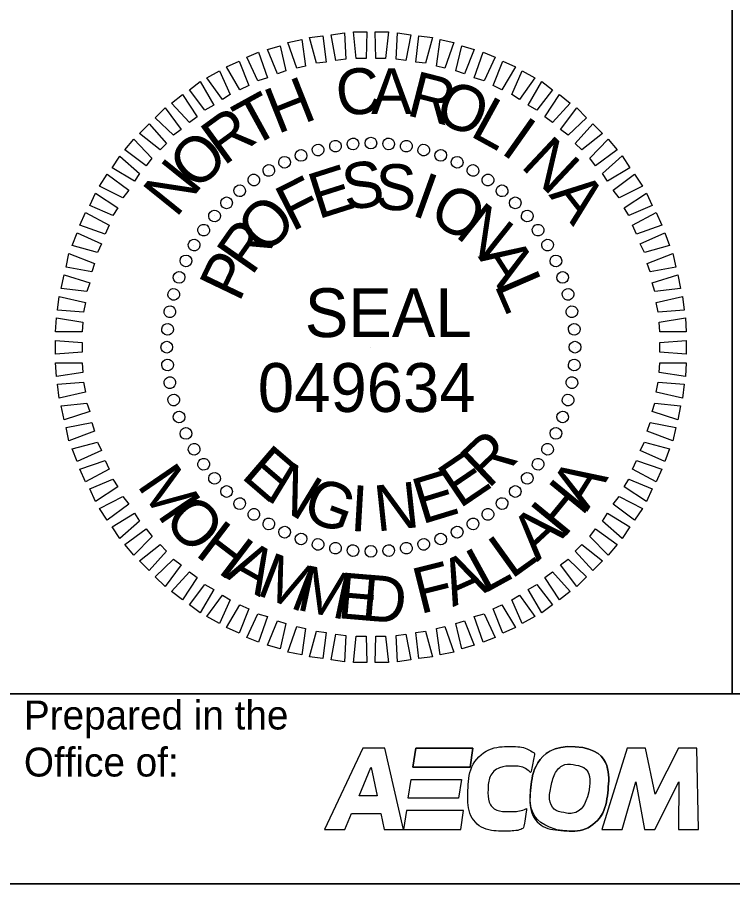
# Model space of a CAD drawing. Extents: x 2113763 to 2114783, y 714280 to 714940.
# Drawn here: x 2114643.5 to 2114702.8, y 714819.5 to 714891.4 of the extents above; entities that cross this region are included whole.
import ezdxf

# ---------------------------------------------------------------- set-up
doc = ezdxf.new("R2010")
doc.units = 0
for name, color, linetype in [('Default', 7, 'Continuous'), ('Prop DSN Text', 7, 'Continuous'), ('Sheet Block Title CELL', 7, 'Continuous'), ('Sheet Border Standard 30in CELL', 7, 'Continuous'), ('Sheet Professional Seal CELL', 7, 'Continuous'), ('Sheet Sticker Exception Certification CELL', 7, 'Continuous')]:
    doc.layers.add(name, color=color, linetype=linetype)

# ---------------------------------------------------------------- blocks, each defined once
blk = doc.blocks.new('block 3')
at = {"layer": 'Default'}
blk.add_open_spline([(0.12275, 0.09393), (0.12554, 0.09373), (0.12726, 0.09146), (0.12695, 0.08843), (0.12663, 0.08531), (0.12411, 0.08298), (0.12127, 0.08318), (0.11848, 0.08338), (0.11676, 0.08565), (0.11707, 0.08868), (0.11739, 0.0918), (0.11991, 0.09413), (0.12275, 0.09393)], degree=3, dxfattribs=at)
blk = doc.blocks.new('block 2')
at = {"layer": 'Default'}
for p, q in [((0.10234, 0.09375), (0.10197, 0.09133)), ((0.10966, 0.09375), (0.10234, 0.09375)), ((0.10929, 0.09133), (0.10966, 0.09375)), ((0.10197, 0.09133), (0.10929, 0.09133)), ((0.10137, 0.08733), (0.10174, 0.08975)), ((0.10174, 0.08975), (0.10818, 0.08975)), ((0.10818, 0.08975), (0.10782, 0.08733)), ((0.10782, 0.08733), (0.10137, 0.08733)), ((0.10114, 0.08576), (0.10078, 0.08333)), ((0.10846, 0.08576), (0.10114, 0.08576)), ((0.1081, 0.08333), (0.10846, 0.08576)), ((0.10078, 0.08333), (0.1081, 0.08333))]:
    blk.add_line(p, q, dxfattribs=at)
for points in [[(0.10929, 0.09133), (0.10197, 0.09133), (0.10234, 0.09375), (0.10966, 0.09375), (0.10929, 0.09133)], [(0.10782, 0.08733), (0.10137, 0.08733), (0.10174, 0.08975), (0.10818, 0.08975), (0.10782, 0.08733)], [(0.10846, 0.08576), (0.10114, 0.08576), (0.10078, 0.08333), (0.1081, 0.08333), (0.10846, 0.08576)]]:
    blk.add_lwpolyline(points, dxfattribs=at)
blk = doc.blocks.new('POINT_DISPLAY')
at = {"layer": 'Default'}
blk.add_line((0, 0), (0, 0), dxfattribs=at)

msp = doc.modelspace()

# ---------------------------------------------------------------- linework, layer by layer
at = {"layer": 'Prop DSN Text'}
for p, q in [((2114672.112, 714830.749), (2114668.936, 714823.999)), ((2114673.94, 714830.749), (2114672.112, 714830.749)), ((2114675.5, 714823.999), (2114673.94, 714830.749)), ((2114694.058, 714830.75), (2114691.961, 714823.999)), ((2114695.578, 714830.75), (2114694.058, 714830.75)), ((2114696.365, 714826.942), (2114695.578, 714830.75)), ((2114698.313, 714830.75), (2114696.365, 714826.942)), ((2114699.835, 714830.75), (2114698.313, 714830.75)), ((2114699.959, 714823.999), (2114699.835, 714830.75)), ((2114671.807, 714826.802), (2114672.787, 714829.143)), ((2114672.787, 714829.143), (2114672.802, 714829.143)), ((2114672.802, 714829.143), (2114673.299, 714826.802)), ((2114693.638, 714823.999), (2114694.78, 714827.951)), ((2114694.78, 714827.951), (2114695.497, 714823.999)), ((2114696.352, 714823.999), (2114698.33, 714827.949)), ((2114698.33, 714827.949), (2114698.307, 714823.999)), ((2114673.299, 714826.802), (2114671.807, 714826.802)), ((2114670.634, 714823.999), (2114671.185, 714825.314)), ((2114671.185, 714825.314), (2114673.615, 714825.314)), ((2114673.615, 714825.314), (2114673.894, 714823.999)), ((2114668.936, 714823.999), (2114670.634, 714823.999)), ((2114673.894, 714823.999), (2114675.5, 714823.999)), ((2114691.961, 714823.999), (2114693.638, 714823.999)), ((2114695.497, 714823.999), (2114696.352, 714823.999)), ((2114698.307, 714823.999), (2114699.959, 714823.999))]:
    msp.add_line(p, q, dxfattribs=at)
for points in [[(2114673.894, 714823.999), (2114675.5, 714823.999), (2114673.94, 714830.749), (2114672.112, 714830.749), (2114668.936, 714823.999), (2114670.634, 714823.999), (2114671.185, 714825.314), (2114673.615, 714825.314), (2114673.894, 714823.999)], [(2114699.959, 714823.999), (2114699.835, 714830.75), (2114698.313, 714830.75), (2114696.365, 714826.942), (2114695.578, 714830.75), (2114694.058, 714830.75), (2114691.961, 714823.999), (2114693.638, 714823.999), (2114694.78, 714827.951), (2114695.497, 714823.999), (2114696.352, 714823.999), (2114698.33, 714827.949), (2114698.307, 714823.999), (2114699.959, 714823.999)]]:
    msp.add_lwpolyline(points, dxfattribs=at)
for points in [[(2114685.708, 714825.73), (2114685.255, 714825.521), (2114684.579, 714825.487), (2114684.248, 714825.487), (2114683.18, 714825.487), (2114682.473, 714826.215), (2114682.509, 714827.298), (2114682.547, 714828.442), (2114683.411, 714829.262), (2114684.585, 714829.262), (2114685.14, 714829.262), (2114685.629, 714829.078), (2114686.067, 714828.708), (2114686.067, 714828.708), (2114686.392, 714830.324), (2114686.392, 714830.324), (2114685.721, 714830.719), (2114685.159, 714830.881), (2114684.456, 714830.881), (2114682.513, 714830.881), (2114680.909, 714829.262), (2114680.841, 714827.227), (2114680.776, 714825.254), (2114682.058, 714823.867), (2114683.964, 714823.867), (2114684.295, 714823.867), (2114685.011, 714823.902), (2114685.463, 714824.11), (2114685.463, 714824.11), (2114685.708, 714825.73), (2114685.708, 714825.73)], [(2114685.708, 714825.73), (2114685.255, 714825.521), (2114684.579, 714825.487), (2114684.248, 714825.487), (2114683.18, 714825.487), (2114682.473, 714826.215), (2114682.509, 714827.298), (2114682.547, 714828.442), (2114683.411, 714829.262), (2114684.585, 714829.262), (2114685.14, 714829.262), (2114685.629, 714829.078), (2114686.067, 714828.708), (2114686.067, 714828.708), (2114686.392, 714830.324), (2114686.392, 714830.324), (2114685.721, 714830.719), (2114685.159, 714830.881), (2114684.456, 714830.881), (2114682.513, 714830.881), (2114680.909, 714829.262), (2114680.841, 714827.227), (2114680.776, 714825.254), (2114682.058, 714823.867), (2114683.964, 714823.867), (2114684.295, 714823.867), (2114685.011, 714823.902), (2114685.463, 714824.11), (2114685.463, 714824.11), (2114685.708, 714825.73), (2114685.708, 714825.73)], [(2114688.077, 714824.028), (2114686.692, 714824.442), (2114685.884, 714825.769), (2114686.058, 714827.464), (2114686.266, 714829.489), (2114687.9, 714830.996), (2114689.742, 714830.865)], [(2114689.742, 714830.865), (2114691.548, 714830.736), (2114692.664, 714829.267), (2114692.463, 714827.302), (2114692.255, 714825.278), (2114690.621, 714823.771), (2114688.778, 714823.902), (2114688.531, 714823.92), (2114688.297, 714823.962), (2114688.077, 714824.028)], [(2114690.857, 714827.138), (2114691.102, 714828.279), (2114690.677, 714829.168), (2114689.815, 714829.344), (2114688.867, 714829.539), (2114688.005, 714828.813), (2114687.745, 714827.607), (2114687.499, 714826.465), (2114687.924, 714825.577), (2114688.786, 714825.4), (2114689.735, 714825.206), (2114690.597, 714825.932), (2114690.857, 714827.138)], [(2114690.857, 714827.138), (2114691.102, 714828.279), (2114690.677, 714829.168), (2114689.815, 714829.344), (2114688.867, 714829.539), (2114688.005, 714828.813), (2114687.745, 714827.607), (2114687.499, 714826.465), (2114687.924, 714825.577), (2114688.786, 714825.4), (2114689.735, 714825.206), (2114690.597, 714825.932), (2114690.857, 714827.138)]]:
    msp.add_open_spline(points, degree=3, dxfattribs=at)
at = {"layer": 'Sheet Block Title CELL'}
msp.add_lwpolyline([(2114642.734, 714835.256), (2114762.735, 714835.256), (2114762.735, 714819.507), (2114642.734, 714819.507)], close=True, dxfattribs=at)
at = {"layer": 'Sheet Border Standard 30in CELL'}
for points in [[(2114642.734, 714902.756), (2114702.764, 714902.756), (2114702.764, 714835.256), (2114642.734, 714835.256)], [(2114702.764, 714902.756), (2114762.765, 714902.756), (2114762.765, 714835.256), (2114702.764, 714835.256)]]:
    msp.add_lwpolyline(points, close=True, dxfattribs=at)
at = {"layer": 'Sheet Professional Seal CELL'}
for points in [[(2114668.27, 714887.567), (2114667.696, 714889.694), (2114668.811, 714889.829), (2114669.081, 714887.668)], [(2114669.89, 714887.804), (2114669.486, 714889.931), (2114670.6, 714890.099), (2114670.701, 714887.905)], [(2114671.578, 714887.973), (2114671.343, 714890.167), (2114672.456, 714890.167), (2114672.389, 714887.973)], [(2114673.199, 714887.973), (2114673.132, 714890.167), (2114674.245, 714890.167), (2114674.009, 714887.973)], [(2114674.887, 714887.905), (2114674.988, 714890.099), (2114676.102, 714889.931), (2114675.697, 714887.804)], [(2114676.507, 714887.669), (2114676.777, 714889.83), (2114677.891, 714889.694), (2114677.317, 714887.568)], [(2114665.03, 714886.689), (2114664.219, 714888.714), (2114665.267, 714889.019), (2114665.738, 714886.926)], [(2114666.65, 714887.162), (2114665.907, 714889.289), (2114667.055, 714889.525), (2114667.358, 714887.331)], [(2114678.228, 714887.331), (2114678.533, 714889.525), (2114679.679, 714889.289), (2114678.938, 714887.162)], [(2114679.848, 714886.926), (2114680.321, 714889.019), (2114681.367, 714888.715), (2114680.558, 714886.689)], [(2114663.41, 714886.116), (2114662.498, 714888.074), (2114663.477, 714888.479), (2114664.219, 714886.352)], [(2114681.367, 714886.352), (2114682.11, 714888.479), (2114683.09, 714888.074), (2114682.178, 714886.116)], [(2114661.924, 714885.373), (2114660.81, 714887.263), (2114661.857, 714887.736), (2114662.667, 714885.711)], [(2114682.921, 714885.711), (2114683.73, 714887.736), (2114684.778, 714887.263), (2114683.664, 714885.373)], [(2114660.473, 714884.563), (2114659.191, 714886.351), (2114660.236, 714886.926), (2114661.114, 714884.968)], [(2114684.473, 714884.968), (2114685.352, 714886.926), (2114686.398, 714886.352), (2114685.115, 714884.563)], [(2114659.022, 714883.685), (2114657.738, 714885.373), (2114658.616, 714886.048), (2114659.763, 714884.091)], [(2114685.824, 714884.091), (2114686.972, 714886.049), (2114687.849, 714885.374), (2114686.566, 714883.686)], [(2114657.738, 714882.638), (2114656.253, 714884.26), (2114657.165, 714884.968), (2114658.38, 714883.111)], [(2114687.208, 714883.111), (2114688.423, 714884.968), (2114689.335, 714884.26), (2114687.849, 714882.638)], [(2114656.422, 714881.592), (2114654.903, 714883.043), (2114655.712, 714883.854), (2114657.063, 714882.065)], [(2114688.524, 714882.066), (2114689.874, 714883.854), (2114690.685, 714883.044), (2114689.166, 714881.593)], [(2114655.309, 714880.378), (2114653.586, 714881.728), (2114654.397, 714882.537), (2114655.848, 714880.917)], [(2114689.74, 714880.917), (2114691.191, 714882.537), (2114692.001, 714881.728), (2114690.28, 714880.378)], [(2114654.16, 714879.06), (2114652.371, 714880.378), (2114653.114, 714881.255), (2114654.633, 714879.702)], [(2114690.955, 714879.703), (2114692.474, 714881.255), (2114693.217, 714880.378), (2114691.428, 714879.061)], [(2114653.181, 714877.778), (2114651.324, 714878.892), (2114651.966, 714879.871), (2114653.586, 714878.419)], [(2114692.001, 714878.419), (2114693.622, 714879.872), (2114694.263, 714878.892), (2114692.406, 714877.778)], [(2114652.203, 714876.393), (2114650.278, 714877.373), (2114650.92, 714878.352), (2114652.709, 714877.035)], [(2114692.879, 714877.036), (2114694.668, 714878.352), (2114695.31, 714877.373), (2114693.386, 714876.394)], [(2114651.392, 714874.942), (2114649.468, 714875.753), (2114649.941, 714876.799), (2114651.797, 714875.584)], [(2114693.791, 714875.584), (2114695.648, 714876.799), (2114696.119, 714875.753), (2114694.195, 714874.942)], [(2114650.751, 714873.39), (2114648.658, 714874.132), (2114649.13, 714875.179), (2114651.089, 714874.133)], [(2114694.499, 714874.133), (2114696.457, 714875.179), (2114696.93, 714874.133), (2114694.837, 714873.39)], [(2114650.109, 714871.871), (2114648.016, 714872.445), (2114648.422, 714873.491), (2114650.447, 714872.579)], [(2114695.141, 714872.579), (2114697.167, 714873.491), (2114697.571, 714872.445), (2114695.479, 714871.871)], [(2114649.636, 714870.251), (2114647.51, 714870.655), (2114647.746, 714871.77), (2114649.873, 714870.959)], [(2114695.714, 714870.959), (2114697.842, 714871.77), (2114698.077, 714870.655), (2114695.95, 714870.251)], [(2114649.232, 714868.629), (2114647.105, 714868.866), (2114647.341, 714870.014), (2114649.468, 714869.339)], [(2114696.119, 714869.339), (2114698.246, 714870.014), (2114698.482, 714868.866), (2114696.356, 714868.629)], [(2114648.961, 714866.908), (2114646.802, 714867.077), (2114646.936, 714868.225), (2114649.13, 714867.719)], [(2114696.457, 714867.719), (2114698.651, 714868.225), (2114698.787, 714867.077), (2114696.626, 714866.909)], [(2114648.827, 714865.288), (2114646.633, 714865.288), (2114646.701, 714866.435), (2114648.895, 714866.098)], [(2114696.694, 714866.098), (2114698.888, 714866.435), (2114698.955, 714865.288), (2114696.761, 714865.288)], [(2114648.827, 714863.6), (2114646.633, 714863.432), (2114646.633, 714864.578), (2114648.827, 714864.41)], [(2114696.761, 714864.41), (2114698.955, 714864.579), (2114698.956, 714863.432), (2114696.761, 714863.601)], [(2114648.895, 714861.913), (2114646.701, 714861.575), (2114646.633, 714862.722), (2114648.827, 714862.722)], [(2114696.761, 714862.722), (2114698.955, 714862.722), (2114698.888, 714861.575), (2114696.694, 714861.913)], [(2114649.13, 714860.292), (2114646.936, 714859.786), (2114646.802, 714860.933), (2114648.961, 714861.102)], [(2114696.626, 714861.102), (2114698.787, 714860.934), (2114698.651, 714859.786), (2114696.457, 714860.293)], [(2114649.468, 714858.671), (2114647.341, 714857.996), (2114647.105, 714859.144), (2114649.232, 714859.381)], [(2114696.356, 714859.381), (2114698.483, 714859.145), (2114698.246, 714857.996), (2114696.12, 714858.672)], [(2114649.873, 714857.051), (2114647.747, 714856.242), (2114647.51, 714857.355), (2114649.637, 714857.761)], [(2114695.951, 714857.761), (2114698.077, 714857.356), (2114697.842, 714856.242), (2114695.714, 714857.051)], [(2114650.447, 714855.431), (2114648.422, 714854.519), (2114648.016, 714855.566), (2114650.11, 714856.139)], [(2114695.479, 714856.14), (2114697.571, 714855.567), (2114697.167, 714854.52), (2114695.141, 714855.431)], [(2114651.089, 714853.879), (2114649.13, 714852.831), (2114648.658, 714853.879), (2114650.752, 714854.62)], [(2114694.837, 714854.62), (2114696.93, 714853.879), (2114696.457, 714852.832), (2114694.499, 714853.879)], [(2114651.798, 714852.426), (2114649.941, 714851.211), (2114649.468, 714852.257), (2114651.392, 714853.068)], [(2114694.195, 714853.068), (2114696.119, 714852.258), (2114695.648, 714851.212), (2114693.791, 714852.426)], [(2114652.709, 714850.975), (2114650.92, 714849.659), (2114650.279, 714850.637), (2114652.203, 714851.617)], [(2114693.386, 714851.617), (2114695.31, 714850.638), (2114694.668, 714849.659), (2114692.88, 714850.975)], [(2114653.586, 714849.591), (2114651.966, 714848.14), (2114651.325, 714849.118), (2114653.181, 714850.232)], [(2114692.406, 714850.232), (2114694.263, 714849.119), (2114693.622, 714848.14), (2114692.001, 714849.592)], [(2114654.634, 714848.309), (2114653.115, 714846.755), (2114652.372, 714847.634), (2114654.161, 714848.949)], [(2114691.428, 714848.95), (2114693.217, 714847.634), (2114692.474, 714846.756), (2114690.955, 714848.309)], [(2114655.848, 714847.093), (2114654.397, 714845.473), (2114653.587, 714846.283), (2114655.309, 714847.634)], [(2114690.28, 714847.634), (2114692.001, 714846.284), (2114691.192, 714845.473), (2114689.74, 714847.093)], [(2114657.063, 714845.946), (2114655.713, 714844.156), (2114654.903, 714844.967), (2114656.422, 714846.418)], [(2114689.166, 714846.418), (2114690.685, 714844.967), (2114689.875, 714844.156), (2114688.524, 714845.946)], [(2114658.38, 714844.899), (2114657.165, 714843.042), (2114656.254, 714843.752), (2114657.738, 714845.372)], [(2114687.849, 714845.372), (2114689.335, 714843.752), (2114688.423, 714843.042), (2114687.209, 714844.899)], [(2114659.764, 714843.921), (2114658.617, 714841.962), (2114657.738, 714842.637), (2114659.022, 714844.325)], [(2114686.567, 714844.325), (2114687.849, 714842.637), (2114686.972, 714841.962), (2114685.824, 714843.921)], [(2114661.114, 714843.042), (2114660.237, 714841.085), (2114659.191, 714841.659), (2114660.473, 714843.447)], [(2114685.115, 714843.448), (2114686.398, 714841.659), (2114685.352, 714841.085), (2114684.474, 714843.042)], [(2114662.667, 714842.299), (2114661.857, 714840.274), (2114660.811, 714840.747), (2114661.925, 714842.637)], [(2114683.664, 714842.637), (2114684.778, 714840.747), (2114683.731, 714840.274), (2114682.921, 714842.3)], [(2114664.22, 714841.659), (2114663.477, 714839.532), (2114662.499, 714839.936), (2114663.41, 714841.895)], [(2114682.178, 714841.895), (2114683.09, 714839.936), (2114682.111, 714839.532), (2114681.368, 714841.659)], [(2114665.739, 714841.085), (2114665.267, 714838.991), (2114664.22, 714839.296), (2114665.03, 714841.321)], [(2114667.359, 714840.679), (2114667.056, 714838.485), (2114665.907, 714838.722), (2114666.65, 714840.848)], [(2114678.938, 714840.848), (2114679.68, 714838.722), (2114678.533, 714838.485), (2114678.228, 714840.679)], [(2114680.558, 714841.321), (2114681.368, 714839.296), (2114680.322, 714838.991), (2114679.849, 714841.085)], [(2114669.081, 714840.342), (2114668.811, 714838.182), (2114667.696, 714838.316), (2114668.271, 714840.443)], [(2114670.701, 714840.105), (2114670.6, 714837.911), (2114669.486, 714838.08), (2114669.891, 714840.207)], [(2114672.389, 714840.039), (2114672.457, 714837.845), (2114671.343, 714837.845), (2114671.578, 714840.039)], [(2114674.009, 714840.039), (2114674.246, 714837.845), (2114673.132, 714837.845), (2114673.2, 714840.039)], [(2114675.697, 714840.208), (2114676.102, 714838.08), (2114674.989, 714837.911), (2114674.888, 714840.105)], [(2114677.317, 714840.443), (2114677.891, 714838.316), (2114676.777, 714838.182), (2114676.508, 714840.342)]]:
    msp.add_lwpolyline(points, close=True, dxfattribs=at)
for centre, major_axis in [((2114669.85, 714880.686), (-0.084, 0.479)), ((2114671.314, 714880.879), (-0.042, 0.484)), ((2114672.79, 714880.944), (0, 0.486)), ((2114674.266, 714880.879), (0.042, 0.484)), ((2114675.73, 714880.686), (0.084, 0.479)), ((2114666.999, 714879.922), (-0.166, 0.457)), ((2114668.408, 714880.367), (-0.126, 0.47)), ((2114677.172, 714880.367), (0.126, 0.47)), ((2114678.581, 714879.922), (0.166, 0.457)), ((2114665.634, 714879.357), (-0.205, 0.441)), ((2114679.946, 714879.357), (0.205, 0.441)), ((2114664.324, 714878.675), (-0.243, 0.421)), ((2114681.256, 714878.675), (0.243, 0.421)), ((2114663.078, 714877.881), (-0.279, 0.398)), ((2114682.502, 714877.881), (0.279, 0.398)), ((2114661.906, 714876.982), (-0.312, 0.372)), ((2114683.674, 714876.982), (0.312, 0.372)), ((2114660.817, 714875.984), (-0.344, 0.344)), ((2114684.763, 714875.984), (0.344, 0.344)), ((2114659.819, 714874.895), (-0.372, 0.312)), ((2114685.761, 714874.895), (0.372, 0.312)), ((2114658.92, 714873.723), (-0.398, 0.279)), ((2114686.66, 714873.723), (0.398, 0.279)), ((2114658.126, 714872.477), (-0.421, 0.243)), ((2114687.454, 714872.478), (0.421, 0.243)), ((2114657.444, 714871.167), (-0.441, 0.205)), ((2114688.136, 714871.167), (0.441, 0.205)), ((2114656.879, 714869.802), (-0.457, 0.166)), ((2114688.701, 714869.803), (0.457, 0.166)), ((2114656.435, 714868.394), (-0.47, 0.126)), ((2114689.145, 714868.394), (0.47, 0.126)), ((2114656.115, 714866.951), (-0.479, 0.084)), ((2114689.465, 714866.952), (0.479, 0.084)), ((2114655.922, 714865.487), (-0.484, 0.042)), ((2114689.658, 714865.487), (0.484, 0.042)), ((2114655.858, 714864.011), (-0.486, 0)), ((2114689.722, 714864.011), (0.486, 0)), ((2114655.922, 714862.535), (-0.484, -0.042)), ((2114689.658, 714862.536), (0.484, -0.042)), ((2114656.115, 714861.071), (-0.479, -0.084)), ((2114689.465, 714861.071), (0.479, -0.084)), ((2114656.435, 714859.629), (-0.47, -0.126)), ((2114689.145, 714859.629), (0.47, -0.126)), ((2114656.879, 714858.22), (-0.457, -0.166)), ((2114688.701, 714858.22), (0.457, -0.166)), ((2114657.444, 714856.855), (-0.441, -0.205)), ((2114688.136, 714856.856), (0.441, -0.205)), ((2114658.126, 714855.545), (-0.421, -0.243)), ((2114687.454, 714855.545), (0.421, -0.243)), ((2114658.92, 714854.299), (-0.398, -0.279)), ((2114686.66, 714854.299), (0.398, -0.279)), ((2114659.819, 714853.127), (-0.372, -0.312)), ((2114685.761, 714853.128), (0.372, -0.312)), ((2114660.817, 714852.038), (-0.344, -0.344)), ((2114684.763, 714852.038), (0.344, -0.344)), ((2114661.906, 714851.04), (-0.312, -0.372)), ((2114683.674, 714851.041), (0.312, -0.372)), ((2114663.078, 714850.141), (-0.279, -0.398)), ((2114682.502, 714850.141), (0.279, -0.398)), ((2114664.324, 714849.347), (-0.243, -0.421)), ((2114681.256, 714849.348), (0.243, -0.421)), ((2114665.634, 714848.665), (-0.205, -0.441)), ((2114666.999, 714848.1), (-0.166, -0.457)), ((2114678.581, 714848.1), (0.166, -0.457)), ((2114679.946, 714848.666), (0.205, -0.441)), ((2114668.408, 714847.656), (-0.126, -0.47)), ((2114677.173, 714847.656), (0.126, -0.47)), ((2114669.85, 714847.336), (-0.084, -0.479)), ((2114671.314, 714847.143), (-0.042, -0.484)), ((2114672.79, 714847.079), (0, -0.486)), ((2114674.266, 714847.144), (0.042, -0.484)), ((2114675.73, 714847.336), (0.084, -0.479))]:
    msp.add_ellipse(centre, major_axis=major_axis, ratio=0.999708, dxfattribs=at)
at = {"layer": 'Sheet Sticker Exception Certification CELL'}
msp.add_line((2114642.734, 714819.507), (2114762.757, 714819.507), dxfattribs=at)

# ---------------------------------------------------------------- block references
at = {"layer": 'Prop DSN Text', "xscale": 648.001866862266, "yscale": 648.0018668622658, "rotation": 1.3379890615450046e-09}
for name in ['block 2', 'block 3']:
    msp.add_blockref(name, (2114610.197, 714769.999), dxfattribs=at)
at = {"layer": 'Sheet Professional Seal CELL', "xscale": 41.411959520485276, "yscale": 41.41195952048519, "rotation": 0.00042986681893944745}
for p in [(2114668.406, 714880.378), (2114669.857, 714880.681), (2114671.308, 714880.884), (2114672.794, 714880.95), (2114674.279, 714880.884), (2114675.731, 714880.681), (2114677.182, 714880.378), (2114666.988, 714879.938), (2114678.6, 714879.938), (2114665.638, 714879.365), (2114679.951, 714879.365), (2114664.321, 714878.69), (2114681.267, 714878.69), (2114663.073, 714877.879), (2114682.516, 714877.879), (2114661.891, 714877.002), (2114683.697, 714877.002), (2114660.811, 714875.989), (2114684.778, 714875.989), (2114659.798, 714874.909), (2114685.79, 714874.909), (2114658.919, 714873.727), (2114686.667, 714873.727), (2114658.11, 714872.478), (2114687.478, 714872.478), (2114657.435, 714871.161), (2114688.153, 714871.161), (2114656.861, 714869.811), (2114688.727, 714869.811), (2114656.422, 714868.394), (2114689.166, 714868.394), (2114656.118, 714866.941), (2114655.916, 714865.49), (2114689.673, 714865.49), (2114655.848, 714864.006), (2114672.794, 714864.006), (2114689.74, 714864.006), (2114655.916, 714862.52), (2114689.673, 714862.52), (2114656.118, 714861.068), (2114689.469, 714861.069), (2114656.422, 714859.617), (2114689.166, 714859.618), (2114656.861, 714858.199), (2114688.728, 714858.199), (2114688.153, 714856.849), (2114687.478, 714855.532), (2114658.92, 714854.283), (2114686.668, 714854.283), (2114659.798, 714853.101), (2114685.791, 714853.101), (2114660.811, 714852.022), (2114684.778, 714852.022), (2114661.891, 714851.009), (2114683.697, 714851.01), (2114663.073, 714850.131), (2114682.516, 714850.131), (2114664.321, 714849.322), (2114665.638, 714848.647), (2114679.951, 714848.647), (2114681.267, 714849.322), (2114666.988, 714848.072), (2114678.601, 714848.072), (2114668.406, 714847.634), (2114669.857, 714847.33), (2114675.731, 714847.33), (2114677.183, 714847.634), (2114671.308, 714847.128), (2114672.794, 714847.06), (2114674.279, 714847.128)]:
    msp.add_blockref('POINT_DISPLAY', p, dxfattribs=at)

# ---------------------------------------------------------------- texts
at = {"layer": 'Prop DSN Text'}
for s, height, p in [('Prepared in the ', 2.40001, (2114644.007, 714832.296)), ('Office of:', 2.4, (2114644.007, 714828.396))]:
    msp.add_text(s, height=height, rotation=0, dxfattribs=at).set_placement(p)
at = {"layer": 'Sheet Professional Seal CELL'}
for s, height, rotation, p in [('C', 3.806, 7.2203, (2114670.134, 714883.112)), ('A', 3.806, 0.02075, (2114672.803, 714883.348)), ('R', 3.806, 345.62153, (2114675.635, 714883.278)), ('H', 3.806, 21.61991, (2114665.031, 714881.66)), ('T', 3.806, 28.8202, (2114662.838, 714880.513)), ('O', 3.806, 338.42159, (2114677.9, 714882.803)), ('L', 3.806, 331.2213, (2114680.902, 714881.589)), ('R', 3.806, 36.02094, (2114660.579, 714878.996)), ('I', 3.806, 324.781, (2114683.454, 714880.18)), ('O', 3.806, 43.22217, (2114658.286, 714876.873)), ('N', 3.806, 316.81934, (2114685.118, 714878.99)), ('N', 3.806, 51.1609, (2114656.624, 714874.67)), ('E', 3.807, 17.6115, (2114668.403, 714874.603)), ('S', 3.807, 8.25604, (2114670.701, 714875.347)), ('S', 3.807, 358.90083, (2114673.132, 714875.415)), ('F', 3.807, 26.96746, (2114666.242, 714873.557)), ('I', 3.807, 340.19003, (2114676.039, 714875.008)), ('A', 3.806, 308.06255, (2114687.494, 714876.634)), ('O', 3.807, 330.83391, (2114677.427, 714874.532)), ('O', 3.807, 45.68167, (2114664.057, 714871.54)), ('N', 3.807, 321.47704, (2114679.683, 714873.252)), ('R', 3.807, 55.04008, (2114662.907, 714869.85)), ('A', 3.807, 302.7607, (2114681.643, 714871.526)), ('P', 3.807, 64.39932, (2114661.859, 714867.656)), ('L', 3.807, 293.40128, (2114682.992, 714869.196)), ('SEAL', 4.0496, 0.00043, (2114667.307, 714864.85)), ('049634', 4.0508, 0.00043, (2114663.409, 714858.638)), ('R', 3.807, 43.48184, (2114682.521, 714852.196)), ('E', 3.807, 319.27732, (2114661.922, 714853.239)), ('E', 3.807, 34.12452, (2114680.15, 714850.568)), ('M', 3.807, 304.41113, (2114653.327, 714852.562)), ('N', 3.807, 328.63439, (2114663.953, 714851.446)), ('E', 3.807, 16.96729, (2114677.006, 714849.294)), ('A', 3.807, 57.87872, (2114690.74, 714850.349)), ('G', 3.807, 339.50364, (2114666.923, 714849.836)), ('H', 3.807, 50.68353, (2114688.783, 714848.08)), ('I', 3.807, 356.70163, (2114671.01, 714848.78)), ('N', 3.807, 6.05682, (2114673.27, 714848.713)), ('O', 3.807, 313.50721, (2114655.44, 714849.53)), ('A', 3.807, 42.87926, (2114686.594, 714846.167)), ('H', 3.807, 322.66556, (2114658.113, 714846.805)), ('L', 3.807, 35.69399, (2114684.444, 714844.716)), ('A', 3.807, 330.54958, (2114660.627, 714844.932)), ('L', 3.807, 28.72874, (2114682.184, 714843.534)), ('M', 3.807, 338.92584, (2114663.194, 714843.512)), ('A', 3.807, 23.98385, (2114679.583, 714842.436)), ('M', 3.807, 348.01683, (2114666.519, 714842.256)), ('F', 3.807, 14.0832, (2114676.863, 714841.859)), ('E', 3.807, 355.14349, (2114669.941, 714841.547)), ('D', 3.807, 355.14349, (2114671.931, 714841.383))]:
    msp.add_text(s, height=height, rotation=rotation, dxfattribs=at).set_placement(p)

doc.saveas('drawing.dxf')
